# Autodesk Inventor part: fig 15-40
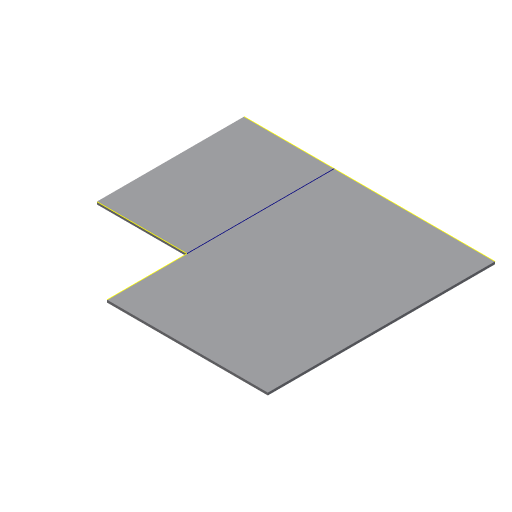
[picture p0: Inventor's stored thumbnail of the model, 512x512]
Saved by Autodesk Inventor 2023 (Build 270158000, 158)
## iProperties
Created: 2005-03
Part Number: fig 15-40
Document SubType Name: Sheet Metal
Designer: CADCIM
Manufacturer: Standard
Standards Organization: Custom
Density: 1 g/cm^3
Sheet Metal Rule: Default
Material: Generic
Appearance: Default
Author: CADCIM
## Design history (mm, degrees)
node "Face1"
  sketch "Sketch1"
    geometry: L1 (31.393, 35.714)-(-19.875, 35.714); L2 (-19.875, 35.714)-(-19.875, 5.625); L3 (-19.875, 5.625)-(-1.5, 5.625); L4 (-1.5, 5.625)-(-1.5, -10.705); L5 (-1.5, -10.705)-(31.393, -10.705); L6 (31.393, -10.705)-(31.393, 35.714)
    constraints: 12 end point, 4 parallel, 1 horizontal, 1 perpendicular
sketch "Sketch3"
  geometry: L1 (18.375, -30.089)-(18.375, 0); L2 (18.375, -46.42)-(18.375, -30.089) reference; L3 (18.375, -30.089)-(0, -30.089) reference; L4 (0, 0)-(51.268, 0) reference
  constraints: 3 point on line, 2 end point, 1 vertical
body "Solid1"
face "Plate1" dims "d1" = 0.5 (= Thickness)
other parameters: "Thickness" = 0.5, "BendRadius" = 0.5 (= Thickness), "BendReliefWidth" = 0.5 (= Thickness), "BendReliefDepth" = 0.25 (= 0.5 x Thickness), "CornerReliefSize" = 2 (= 4 x Thickness), "SeamGap" = 0.01, "MinimumRemnant" = 1 (= 2 x Thickness), "TransitionRadius" = 0.5 (= BendRadius), "d0" = 0.5 (= BendRadius), "JacobiRadiusSize" = 0.5 (= Thickness), "GapSize" = 0.5 (= Thickness)
